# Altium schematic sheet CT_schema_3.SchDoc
size 298 x 247 mm
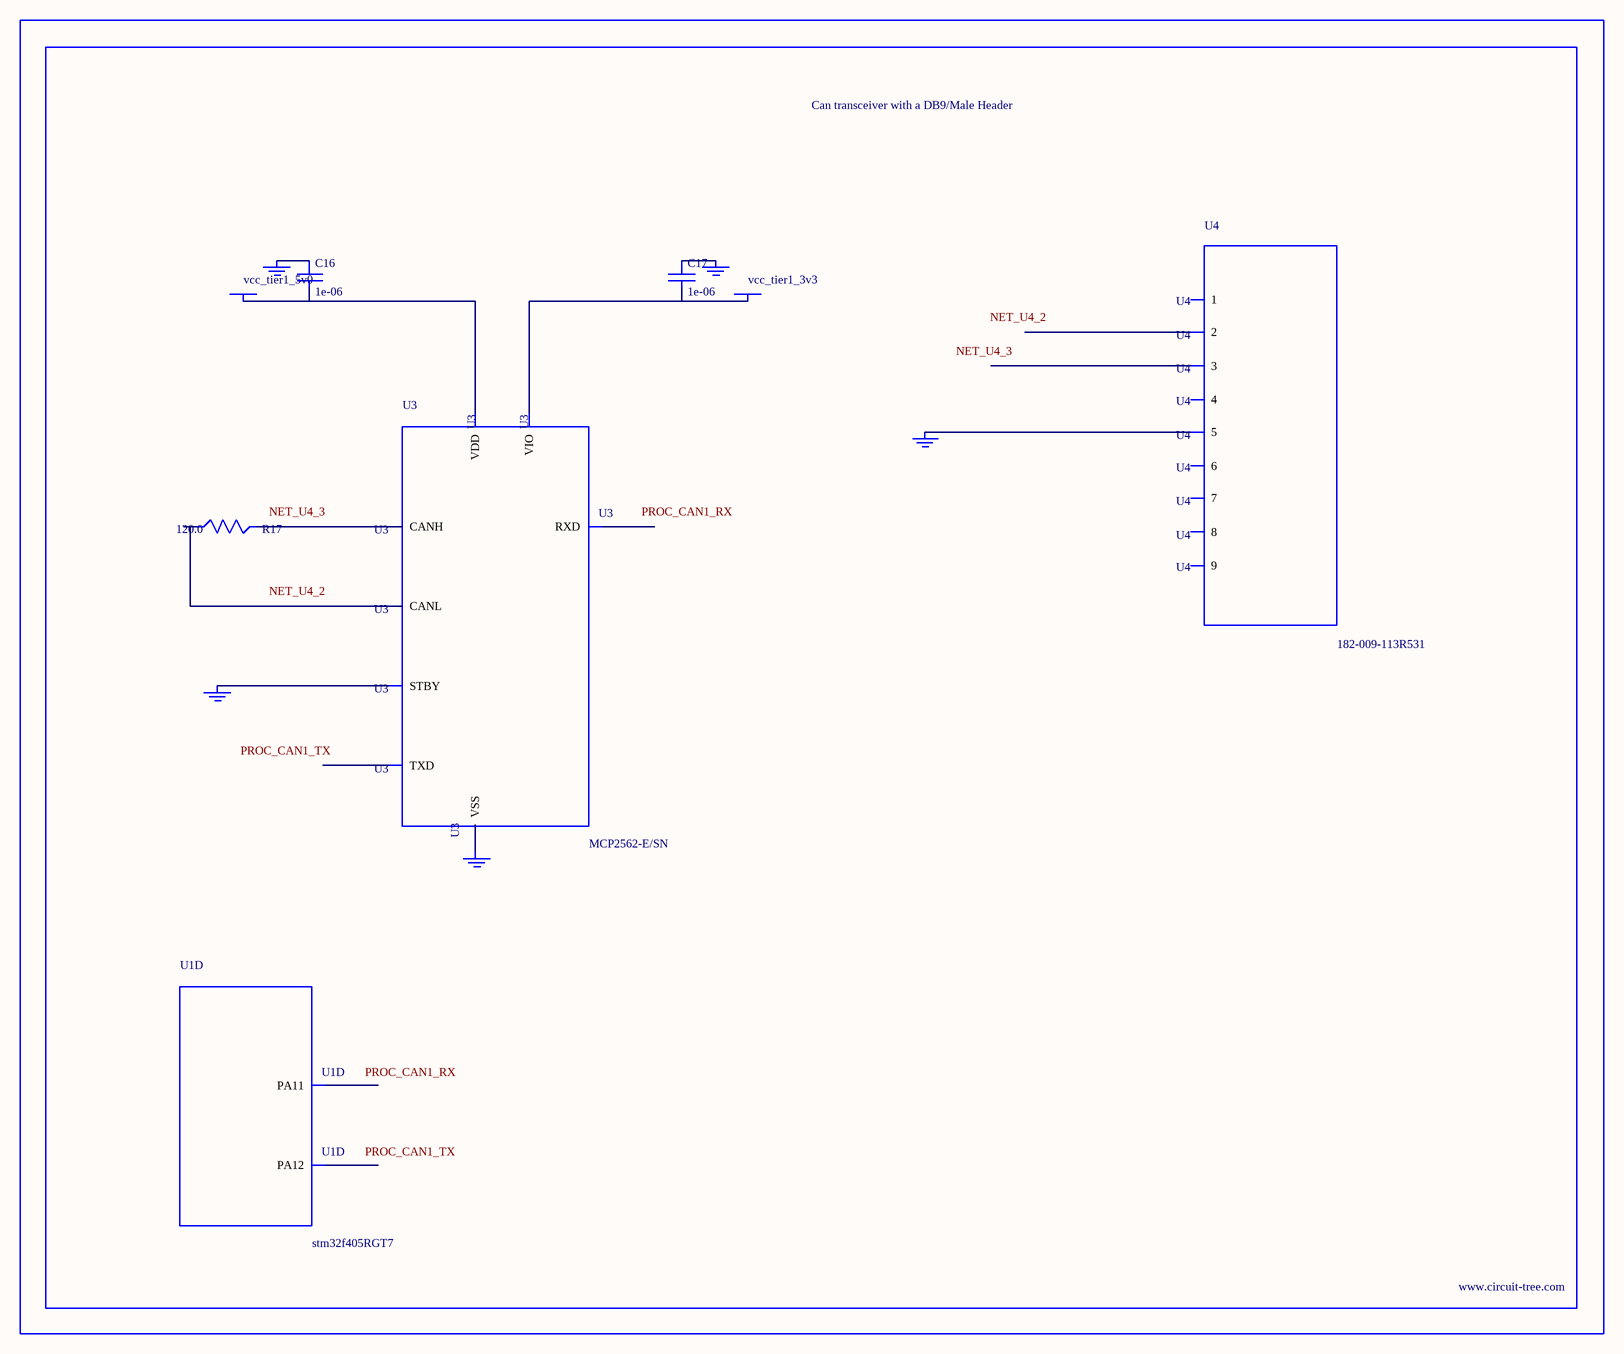
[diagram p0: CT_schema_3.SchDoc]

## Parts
BORDER2  (no value)
C16  1e-06  [C0603]
C17  1e-06  [C0603]
GND_INSTANCE_2_0  (no value)
GND_INSTANCE_2_1  (no value)
GND_INSTANCE_2_2  (no value)
GND_INSTANCE_2_3  (no value)
GND_INSTANCE_2_4  (no value)
POWER_INSTANCE_2_0  vcc_tier1_5v0
POWER_INSTANCE_2_1  vcc_tier1_3v3
R17  120.0  [R0603]
U1  stm32f405RGT7  [LQFP64]  (part D of 6)
U3  MCP2562-E/SN  [SOIC-8]
U4  182-009-113R531  [182-009-MALE]

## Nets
NetC16_1: C16.1 GND_INSTANCE_2_0.0(GND)
NetC16_2: C16.2 POWER_INSTANCE_2_0.0(PWR) U3.3(VDD)
NetC17_1: C17.1 GND_INSTANCE_2_1.0(GND)
NetC17_2: C17.2 POWER_INSTANCE_2_1.0(PWR) U3.5(VIO)
NetGND_INSTANCE_2_2_0: GND_INSTANCE_2_2.0(GND) U3.8(STBY)
NetGND_INSTANCE_2_3_0: GND_INSTANCE_2_3.0(GND) U3.2(VSS)
NetGND_INSTANCE_2_4_0: GND_INSTANCE_2_4.0(GND) U4.5
NetR17_1: R17.1 U3.6(CANL)
NetR17_2: R17.2 U3.7(CANH)

Not connected (* = marked no-connect by the designer): U1 44(PA11) 45(PA12); U3 1(TXD) 4(RXD); U4 1 2 3 4 6 7 8 9

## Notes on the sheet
- Labels drawn without touching a wire or pin: NET_U4_2, NET_U4_3, PROC_CAN1_RX, PROC_CAN1_TX

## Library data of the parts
BORDER2 = BORDER_PAGE2
C16 C17 = C0603C105K3RACTU
GND_INSTANCE_2_0-GND_INSTANCE_2_4 = GND
POWER_INSTANCE_2_0 POWER_INSTANCE_2_1 = PWR
R17 = RC0603JR-07120RL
